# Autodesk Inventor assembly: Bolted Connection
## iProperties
Created: 2006-03
Part Number: Bolted Connection
Document SubType Name: Assembly
Designer: Administrator
ClientObjectVersion: 1
Author: Administrator
